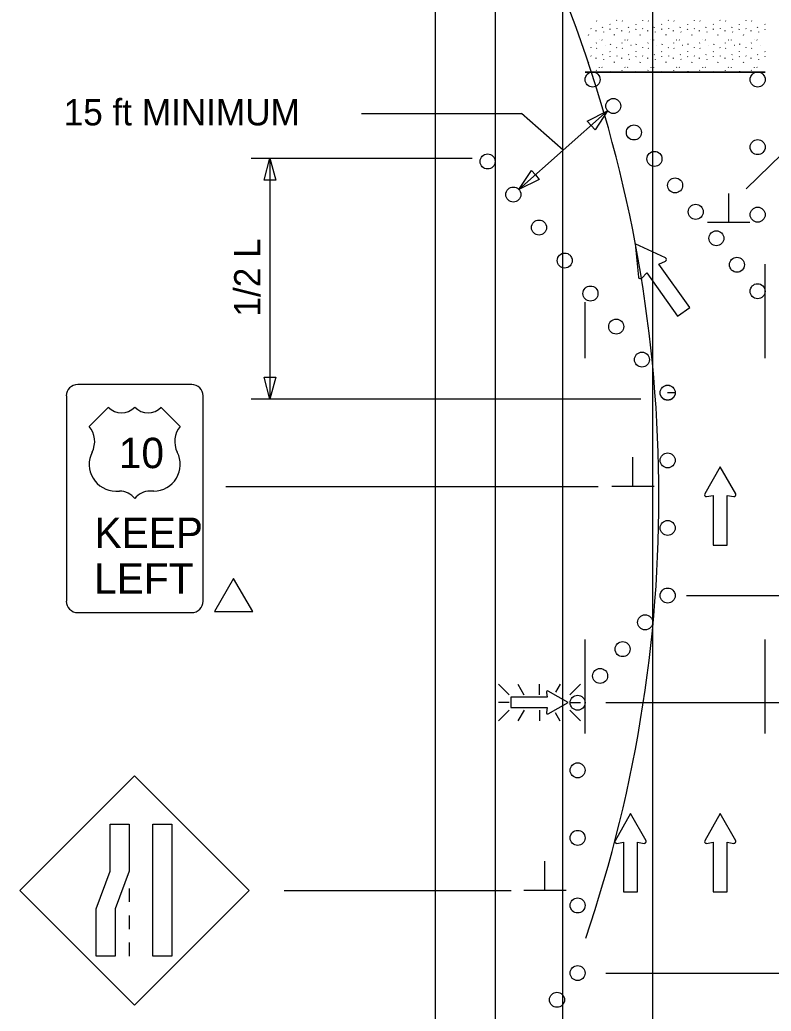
# Model space of a CAD drawing. Extents: x 16604 to 19504, y 6997 to 8305.
# Drawn here: x 16789 to 16989.3, y 7467.1 to 7731.2 of the extents above; entities that cross this region are included whole.
import ezdxf

# ---------------------------------------------------------------- set-up
doc = ezdxf.new("R2010")
doc.units = 0
for name, color, linetype in [('ALI_LEGAL_EX', 7, 'Continuous'), ('MT_SCRATCH_LEVEL_A', 7, 'Continuous'), ('MT_SCRATCH_LEVEL_E', 7, 'Continuous'), ('PAVT_EDGE_EX', 7, 'Continuous'), ('TRAFFIC_SIGNS_PR', 7, 'Continuous'), ('TYPICAL_EX', 7, 'Continuous'), ('TYPICAL_TEXT_DIMEN_PR', 7, 'Continuous')]:
    doc.layers.add(name, color=color, linetype=linetype)

msp = doc.modelspace()

# ---------------------------------------------------------------- linework, layer by layer
at = {"layer": 'ALI_LEGAL_EX'}
for p, q in [((16933.79, 7333.59), (16933.79, 7943.78)), ((16933.79, 7333.59), (16933.79, 7943.78)), ((16957.79, 7333.59), (16957.79, 7943.78))]:
    msp.add_line(p, q, dxfattribs=at)
for points in [[(16987.73, 7641.09), (16987.73, 7666.09)], [(16939.73, 7641.09), (16939.73, 7656.01)], [(16939.73, 7541.09), (16939.73, 7566.09)], [(16987.73, 7541.09), (16987.73, 7566.09)]]:
    msp.add_lwpolyline(points, dxfattribs=at)
msp.add_arc((16595.41, 7604.2), 364, 341.1459, 21.3367, dxfattribs=at)
at = {"layer": 'MT_SCRATCH_LEVEL_A'}
for p, q in [((16942.76, 7730.95), (16942.81, 7730.87)), ((16946.32, 7730.03), (16946.38, 7729.95)), ((16948.11, 7731.09), (16948.17, 7731.01)), ((16949.64, 7730.95), (16949.69, 7730.87)), ((16953.21, 7730.03), (16953.26, 7729.95)), ((16955, 7731.09), (16955.05, 7731.01)), ((16956.53, 7730.95), (16956.58, 7730.87)), ((16960.1, 7730.03), (16960.15, 7729.95)), ((16961.89, 7731.09), (16961.94, 7731.01)), ((16963.42, 7730.95), (16963.47, 7730.87)), ((16966.99, 7730.03), (16967.04, 7729.95)), ((16968.78, 7731.09), (16968.83, 7731.01)), ((16970.31, 7730.95), (16970.36, 7730.87)), ((16973.87, 7730.03), (16973.92, 7729.95)), ((16975.66, 7731.09), (16975.72, 7731.01)), ((16977.19, 7730.95), (16977.24, 7730.87)), ((16980.76, 7730.03), (16980.81, 7729.95)), ((16982.55, 7731.09), (16982.6, 7731.01)), ((16984.08, 7730.95), (16984.13, 7730.87)), ((16987.65, 7730.03), (16987.7, 7729.95)), ((16940.66, 7727.13), (16940.71, 7727.25)), ((16941.28, 7728.88), (16941.33, 7728.8)), ((16942.56, 7728.31), (16942.57, 7728.19)), ((16944.4, 7729.16), (16944.45, 7729.28)), ((16944.59, 7727.96), (16944.64, 7727.89)), ((16946.37, 7728.63), (16946.42, 7728.75)), ((16947.54, 7727.13), (16947.6, 7727.25)), ((16948.16, 7728.88), (16948.21, 7728.8)), ((16949.44, 7728.31), (16949.46, 7728.19)), ((16951.28, 7729.16), (16951.34, 7729.28)), ((16951.47, 7727.96), (16951.53, 7727.89)), ((16953.25, 7728.63), (16953.31, 7728.75)), ((16954.43, 7727.13), (16954.48, 7727.25)), ((16955.05, 7728.88), (16955.1, 7728.8)), ((16956.33, 7728.31), (16956.34, 7728.19)), ((16958.17, 7729.16), (16958.22, 7729.28)), ((16958.36, 7727.96), (16958.41, 7727.89)), ((16960.14, 7728.63), (16960.19, 7728.75)), ((16961.32, 7727.13), (16961.37, 7727.25)), ((16961.94, 7728.88), (16961.99, 7728.8)), ((16963.22, 7728.31), (16963.23, 7728.19)), ((16965.06, 7729.16), (16965.11, 7729.28)), ((16965.25, 7727.96), (16965.3, 7727.89)), ((16967.03, 7728.63), (16967.08, 7728.75)), ((16968.21, 7727.13), (16968.26, 7727.25)), ((16968.83, 7728.88), (16968.88, 7728.8)), ((16970.11, 7728.31), (16970.12, 7728.19)), ((16971.95, 7729.16), (16972, 7729.28)), ((16972.14, 7727.96), (16972.19, 7727.89)), ((16973.92, 7728.63), (16973.97, 7728.75)), ((16975.09, 7727.13), (16975.15, 7727.25)), ((16975.71, 7728.88), (16975.76, 7728.8)), ((16976.99, 7728.31), (16977.01, 7728.19)), ((16978.83, 7729.16), (16978.89, 7729.28)), ((16979.02, 7727.96), (16979.08, 7727.89)), ((16980.8, 7728.63), (16980.85, 7728.75)), ((16981.98, 7727.13), (16982.03, 7727.25)), ((16982.6, 7728.88), (16982.65, 7728.8)), ((16983.88, 7728.31), (16983.89, 7728.19)), ((16985.72, 7729.16), (16985.78, 7729.28)), ((16985.91, 7727.96), (16985.96, 7727.89)), ((16987.69, 7728.63), (16987.73, 7728.72)), ((16942.68, 7724.93), (16942.73, 7725.05)), ((16943.44, 7725.89), (16943.49, 7725.82)), ((16944.18, 7725.86), (16944.23, 7725.78)), ((16945.05, 7724.48), (16945.1, 7724.41)), ((16946.49, 7724.64), (16946.55, 7724.75)), ((16949.56, 7724.93), (16949.62, 7725.05)), ((16950.33, 7725.89), (16950.38, 7725.82)), ((16951.06, 7725.86), (16951.12, 7725.78)), ((16951.93, 7724.48), (16951.99, 7724.41)), ((16953.38, 7724.64), (16953.43, 7724.75)), ((16956.45, 7724.93), (16956.5, 7725.05)), ((16957.22, 7725.89), (16957.27, 7725.82)), ((16957.95, 7725.86), (16958, 7725.78)), ((16958.82, 7724.48), (16958.87, 7724.41)), ((16960.27, 7724.64), (16960.32, 7724.75)), ((16963.34, 7724.93), (16963.39, 7725.05)), ((16964.1, 7725.89), (16964.15, 7725.82)), ((16964.84, 7725.86), (16964.89, 7725.78)), ((16965.71, 7724.48), (16965.76, 7724.41)), ((16967.16, 7724.64), (16967.21, 7724.75)), ((16970.23, 7724.93), (16970.28, 7725.05)), ((16970.99, 7725.89), (16971.04, 7725.82)), ((16971.73, 7725.86), (16971.78, 7725.78)), ((16972.6, 7724.48), (16972.65, 7724.41)), ((16974.05, 7724.64), (16974.1, 7724.75)), ((16977.11, 7724.93), (16977.17, 7725.05)), ((16977.88, 7725.89), (16977.93, 7725.82)), ((16978.62, 7725.86), (16978.67, 7725.78)), ((16979.48, 7724.48), (16979.53, 7724.41)), ((16980.93, 7724.64), (16980.98, 7724.75)), ((16984, 7724.93), (16984.05, 7725.05)), ((16984.76, 7725.89), (16984.82, 7725.82)), ((16985.5, 7725.86), (16985.55, 7725.78)), ((16986.37, 7724.48), (16986.42, 7724.41)), ((16941.23, 7723.81), (16941.28, 7723.73)), ((16941.28, 7721.6), (16941.33, 7721.52)), ((16942.76, 7723.67), (16942.81, 7723.59)), ((16944.4, 7721.88), (16944.45, 7721.99)), ((16946.32, 7722.75), (16946.38, 7722.67)), ((16948.11, 7723.81), (16948.17, 7723.73)), ((16948.16, 7721.6), (16948.21, 7721.52)), ((16949.64, 7723.67), (16949.69, 7723.59)), ((16951.28, 7721.88), (16951.34, 7721.99)), ((16953.21, 7722.75), (16953.26, 7722.67)), ((16955, 7723.81), (16955.05, 7723.73)), ((16955.05, 7721.6), (16955.1, 7721.52)), ((16956.53, 7723.67), (16956.58, 7723.59)), ((16958.17, 7721.88), (16958.22, 7721.99)), ((16960.1, 7722.75), (16960.15, 7722.67)), ((16961.89, 7723.81), (16961.94, 7723.73)), ((16961.94, 7721.6), (16961.99, 7721.52)), ((16963.42, 7723.67), (16963.47, 7723.59)), ((16965.06, 7721.88), (16965.11, 7721.99)), ((16966.99, 7722.75), (16967.04, 7722.67)), ((16968.78, 7723.81), (16968.83, 7723.73)), ((16968.83, 7721.6), (16968.88, 7721.52)), ((16970.31, 7723.67), (16970.36, 7723.59)), ((16971.95, 7721.88), (16972, 7721.99)), ((16973.87, 7722.75), (16973.92, 7722.67)), ((16975.66, 7723.81), (16975.72, 7723.73)), ((16975.71, 7721.6), (16975.76, 7721.52)), ((16977.19, 7723.67), (16977.24, 7723.59)), ((16978.83, 7721.88), (16978.89, 7721.99)), ((16980.76, 7722.75), (16980.81, 7722.67)), ((16982.55, 7723.81), (16982.6, 7723.73)), ((16982.6, 7721.6), (16982.65, 7721.52)), ((16984.08, 7723.67), (16984.13, 7723.59)), ((16985.72, 7721.88), (16985.78, 7721.99)), ((16987.65, 7722.75), (16987.7, 7722.67)), ((16940.66, 7719.84), (16940.71, 7719.96)), ((16942.56, 7721.02), (16942.57, 7720.9)), ((16944.59, 7720.68), (16944.64, 7720.6)), ((16946.37, 7721.35), (16946.42, 7721.46)), ((16947.54, 7719.84), (16947.6, 7719.96)), ((16949.44, 7721.02), (16949.46, 7720.9)), ((16951.47, 7720.68), (16951.53, 7720.6)), ((16953.25, 7721.35), (16953.31, 7721.46)), ((16954.43, 7719.84), (16954.48, 7719.96)), ((16956.33, 7721.02), (16956.34, 7720.9)), ((16958.36, 7720.68), (16958.41, 7720.6)), ((16960.14, 7721.35), (16960.19, 7721.46)), ((16961.32, 7719.84), (16961.37, 7719.96)), ((16963.22, 7721.02), (16963.23, 7720.9)), ((16965.25, 7720.68), (16965.3, 7720.6)), ((16967.03, 7721.35), (16967.08, 7721.46)), ((16968.21, 7719.84), (16968.26, 7719.96)), ((16970.11, 7721.02), (16970.12, 7720.9)), ((16972.14, 7720.68), (16972.19, 7720.6)), ((16973.92, 7721.35), (16973.97, 7721.46)), ((16975.09, 7719.84), (16975.15, 7719.96)), ((16976.99, 7721.02), (16977.01, 7720.9)), ((16979.02, 7720.68), (16979.08, 7720.6)), ((16980.8, 7721.35), (16980.85, 7721.46)), ((16981.98, 7719.84), (16982.03, 7719.96)), ((16983.88, 7721.02), (16983.89, 7720.9)), ((16985.91, 7720.68), (16985.96, 7720.6)), ((16987.69, 7721.35), (16987.73, 7721.43)), ((16987.73, 7717.28), (16939.73, 7717.28)), ((16939.73, 7717.28), (16987.73, 7717.28)), ((16942.68, 7717.65), (16942.73, 7717.76)), ((16943.44, 7718.61), (16943.49, 7718.53)), ((16944.18, 7718.58), (16944.23, 7718.5)), ((16946.49, 7717.35), (16946.55, 7717.47)), ((16949.56, 7717.65), (16949.62, 7717.76)), ((16950.33, 7718.61), (16950.38, 7718.53)), ((16951.06, 7718.58), (16951.12, 7718.5)), ((16953.38, 7717.35), (16953.43, 7717.47)), ((16956.45, 7717.65), (16956.5, 7717.76)), ((16957.22, 7718.61), (16957.27, 7718.53)), ((16957.95, 7718.58), (16958, 7718.5)), ((16960.27, 7717.35), (16960.32, 7717.47)), ((16963.34, 7717.65), (16963.39, 7717.76)), ((16964.1, 7718.61), (16964.15, 7718.53)), ((16964.84, 7718.58), (16964.89, 7718.5)), ((16967.16, 7717.35), (16967.21, 7717.47)), ((16970.23, 7717.65), (16970.28, 7717.76)), ((16970.99, 7718.61), (16971.04, 7718.53)), ((16971.73, 7718.58), (16971.78, 7718.5)), ((16974.05, 7717.35), (16974.1, 7717.47)), ((16977.11, 7717.65), (16977.17, 7717.76)), ((16977.88, 7718.61), (16977.93, 7718.53)), ((16978.62, 7718.58), (16978.67, 7718.5)), ((16980.93, 7717.35), (16980.98, 7717.47)), ((16984, 7717.65), (16984.05, 7717.76)), ((16984.76, 7718.61), (16984.82, 7718.53)), ((16985.5, 7718.58), (16985.55, 7718.5))]:
    msp.add_line(p, q, dxfattribs=at)
at = {"layer": 'MT_SCRATCH_LEVEL_E'}
for p, q in [((16975.73, 7612.12), (16971.62, 7604.88)), ((16979.88, 7604.88), (16975.73, 7612.12)), ((16972.1, 7604.2), (16973.88, 7604.51)), ((16973.88, 7604.51), (16973.88, 7591.26)), ((16977.62, 7591.26), (16977.62, 7604.51)), ((16977.62, 7604.51), (16979.4, 7604.2)), ((16973.88, 7591.26), (16977.62, 7591.26)), ((16951.83, 7519.75), (16947.71, 7512.51)), ((16955.97, 7512.51), (16951.83, 7519.75)), ((16975.73, 7519.75), (16971.62, 7512.51)), ((16979.88, 7512.51), (16975.73, 7519.75)), ((16948.2, 7511.82), (16949.97, 7512.14)), ((16949.97, 7512.14), (16949.97, 7498.88)), ((16953.72, 7498.88), (16953.72, 7512.14)), ((16953.72, 7512.14), (16955.49, 7511.82)), ((16972.1, 7511.82), (16973.88, 7512.14)), ((16973.88, 7512.14), (16973.88, 7498.88)), ((16977.62, 7498.88), (16977.62, 7512.14)), ((16977.62, 7512.14), (16979.4, 7511.82)), ((16949.97, 7498.88), (16953.72, 7498.88)), ((16973.88, 7498.88), (16977.62, 7498.88))]:
    msp.add_line(p, q, dxfattribs=at)
for centre, start, end in [((16972.03, 7604.66), 150.4248, 279.9638), ((16979.47, 7604.66), 260.0362, 29.7731), ((16948.12, 7512.28), 150.4248, 279.9638), ((16955.56, 7512.29), 260.0362, 29.7731), ((16972.03, 7512.28), 150.4248, 279.9638), ((16979.47, 7512.29), 260.0362, 29.7731)]:
    msp.add_arc(centre, 0.463, start, end, dxfattribs=at)
at = {"layer": 'PAVT_EDGE_EX'}
for p, q in [((16899.73, 7751.28), (16899.73, 7396.71)), ((16915.73, 7751.28), (16915.73, 7396.71))]:
    msp.add_line(p, q, dxfattribs=at)
at = {"layer": 'TRAFFIC_SIGNS_PR'}
for p, q in [((16834.86, 7634.03), (16804.48, 7634.03)), ((16801.45, 7631), (16801.45, 7576.32)), ((16837.9, 7576.32), (16837.9, 7631)), ((16804.48, 7573.28), (16834.86, 7573.28)), ((16919.5, 7551.37), (16916.68, 7554.19)), ((16921.8, 7554.19), (16923.43, 7551.37)), ((16927.59, 7551.37), (16927.59, 7554.19)), ((16933.06, 7554.19), (16931.85, 7552.1)), ((16938.49, 7554.19), (16935.67, 7551.37)), ((16919.5, 7549.34), (16916.68, 7549.34)), ((16919.5, 7547.31), (16916.68, 7544.49)), ((16923.45, 7547.31), (16921.83, 7544.49)), ((16927.59, 7547.31), (16927.59, 7544.49)), ((16935.67, 7549.34), (16938.49, 7549.34)), ((16938.49, 7544.49), (16935.67, 7547.31)), ((16931.77, 7546.68), (16933.03, 7544.49)), ((16819.59, 7529.79), (16789.04, 7499.25)), ((16850.14, 7499.25), (16819.59, 7529.79)), ((16818.19, 7499.8), (16818.19, 7496.2)), ((16789.04, 7499.25), (16819.59, 7468.7)), ((16819.59, 7468.7), (16850.14, 7499.25)), ((16818.19, 7492.6), (16818.19, 7489)), ((16818.19, 7485.4), (16818.19, 7481.8))]:
    msp.add_line(p, q, dxfattribs=at)
for points in [[(16929.42, 7552.02), (16929.65, 7550.73), (16919.92, 7550.73), (16919.92, 7547.98), (16929.65, 7547.98), (16929.41, 7546.68)], [(16929.92, 7546.33), (16935.22, 7549.34), (16929.92, 7552.38)]]:
    msp.add_lwpolyline(points, dxfattribs=at)
for points in [[(16818.19, 7516.95), (16818.19, 7504.37), (16814.42, 7494.38), (16814.42, 7481.8), (16809.37, 7481.8), (16809.37, 7494.38), (16813.13, 7504.37), (16813.13, 7516.95)], [(16829.59, 7516.95), (16829.59, 7481.8), (16824.54, 7481.8), (16824.54, 7516.95)]]:
    msp.add_lwpolyline(points, close=True, dxfattribs=at)
for centre in [(16941.73, 7715.28), (16941.73, 7715.28), (16985.72, 7715.28), (16947.23, 7708.23), (16952.73, 7701.18), (16985.72, 7697.28), (16913.73, 7693.45), (16958.22, 7694.14), (16963.72, 7687.09), (16920.59, 7684.65), (16969.21, 7680.04), (16985.72, 7679.28), (16927.44, 7675.86), (16974.71, 7672.99), (16934.3, 7667.06), (16980.2, 7665.94), (16985.7, 7658.89), (16941.16, 7658.27), (16948.01, 7649.47), (16954.87, 7640.68), (16961.73, 7631.88), (16961.73, 7631.83), (16961.73, 7613.83), (16961.73, 7595.83), (16961.73, 7577.83), (16955.73, 7570.69), (16949.73, 7563.55), (16943.73, 7556.41), (16937.73, 7549.27), (16937.73, 7531.27), (16937.73, 7513.27), (16937.73, 7495.27), (16937.73, 7477.27), (16932.23, 7470.14)]:
    msp.add_circle(centre, 2, dxfattribs=at)
for centre, radius, start, end in [((16804.48, 7631), 3.04, 90, 180), ((16834.86, 7631), 3.04, 0, 90), ((16804.48, 7576.32), 3.04, 180, 270), ((16834.86, 7576.32), 3.04, 270, 0), ((16929.75, 7552.08), 0.341, 61.4833, 189.9593), ((16929.75, 7546.63), 0.341, 170.7308, 298.8916)]:
    msp.add_arc(centre, radius, start, end, dxfattribs=at)
at = {"layer": 'TYPICAL_EX'}
for p, q in [((16807.52, 7622.9), (16812.58, 7627.96)), ((16831.82, 7622.9), (16826.76, 7627.96)), ((16814.6, 7605.67), (16815.62, 7605.67)), ((16824.74, 7605.67), (16823.73, 7605.67))]:
    msp.add_line(p, q, dxfattribs=at)
for centre, radius, start, end in [((16816.13, 7631.65), 5.11, 226.1404, 313.8596), ((16823.22, 7631.65), 5.11, 226.1404, 313.8596), ((16802.72, 7618.84), 6.28, 333.0977, 40.1936), ((16836.62, 7618.84), 6.28, 139.8064, 206.9023), ((16814.61, 7612.75), 7.08, 152.6698, 269.9013), ((16824.73, 7612.75), 7.08, 270.0987, 27.3302), ((16815.63, 7600.6), 5.07, 37.1038, 90.1385), ((16823.72, 7600.6), 5.07, 89.8615, 142.8962)]:
    msp.add_arc(centre, radius, start, end, dxfattribs=at)
at = {"layer": 'TYPICAL_TEXT_DIMEN_PR'}
for p, q in [((16880.16, 7706.2), (16922.78, 7706.2)), ((16922.08, 7685.98), (16945.73, 7706.91)), ((16933.91, 7696.44), (16922.78, 7706.2)), ((16940.3, 7704.2), (16945.73, 7706.91)), ((16945.73, 7706.91), (16942.38, 7701.85)), ((16941.34, 7703.02), (16940.3, 7704.2)), ((17002.42, 7705.43), (16982.68, 7686.16)), ((16942.38, 7701.85), (16941.34, 7703.02)), ((16850.73, 7694.34), (16909.63, 7694.34)), ((16854.16, 7688.48), (16855.73, 7694.34)), ((16855.73, 7694.34), (16855.73, 7630.13)), ((16855.73, 7694.34), (16857.3, 7688.48)), ((16922.08, 7685.98), (16925.43, 7691.04)), ((16925.43, 7691.04), (16926.47, 7689.86)), ((16926.47, 7689.86), (16927.52, 7688.69)), ((16855.73, 7688.48), (16854.16, 7688.48)), ((16857.3, 7688.48), (16855.73, 7688.48)), ((16927.52, 7688.69), (16922.08, 7685.98)), ((16978.01, 7677.16), (16978.01, 7684.94)), ((16983.63, 7677.16), (16972.38, 7677.16)), ((16961.14, 7667.78), (16953.06, 7671.5)), ((16953.06, 7671.5), (16953.97, 7662.67)), ((16959.41, 7666.06), (16961.15, 7666.89)), ((16954.81, 7662.37), (16956.16, 7663.75)), ((16956.16, 7663.75), (16964.37, 7652.23)), ((16967.62, 7654.55), (16959.41, 7666.06)), ((16964.37, 7652.23), (16967.62, 7654.55)), ((16855.73, 7630.13), (16854.16, 7635.99)), ((16854.16, 7635.99), (16855.73, 7635.99)), ((16855.73, 7635.99), (16857.3, 7635.99)), ((16857.3, 7635.99), (16855.73, 7630.13)), ((16961.73, 7631.89), (16963.73, 7631.89)), ((16954.62, 7630.13), (16850.73, 7630.13)), ((16952.48, 7606.89), (16952.48, 7614.67)), ((16843.97, 7606.89), (16943.23, 7606.89)), ((16958.1, 7606.89), (16946.85, 7606.89)), ((16966.78, 7577.83), (17106.52, 7577.83)), ((17106.52, 7549.27), (16945.23, 7549.27)), ((16929.01, 7499.27), (16929.01, 7507.06)), ((16859.48, 7499.27), (16920.02, 7499.27)), ((16934.64, 7499.27), (16923.39, 7499.27)), ((16945.23, 7477.27), (17106.52, 7477.27))]:
    msp.add_line(p, q, dxfattribs=at)
msp.add_lwpolyline([(16846.03, 7582.41), (16840.94, 7573.6), (16851.12, 7573.6)], close=True, dxfattribs=at)
for centre, start, end in [((16960.93, 7667.33), 295.5061, 65.243), ((16954.46, 7662.72), 185.8947, 315.4337)]:
    msp.add_arc(centre, 0.494, start, end, dxfattribs=at)

# ---------------------------------------------------------------- texts
at = {"layer": 'TRAFFIC_SIGNS_PR'}
for s, p in [('10', (16815.44, 7611.76)), ('KEEP', (16808.96, 7590.5)), ('LEFT', (16808.85, 7578.35))]:
    msp.add_text(s, height=8.1, dxfattribs=at).set_placement(p)
at = {"layer": 'TYPICAL_TEXT_DIMEN_PR'}
msp.add_text('15 ft MINIMUM', height=7, dxfattribs=at).set_placement((16800.75, 7703.07))
msp.add_text('1/2 L', height=7, rotation=90, dxfattribs=at).set_placement((16853.17, 7652.14))

doc.saveas('drawing.dxf')
